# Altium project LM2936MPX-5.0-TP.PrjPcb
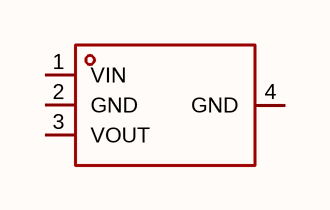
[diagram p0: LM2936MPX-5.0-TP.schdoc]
1 sheet, 1 parts. Net scope: global (net labels, ports and power ports of the same name join across sheets).

## Sheet LM2936MPX-5.0-TP.schdoc
size 127 x 101 mm

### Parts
U?  lm2936mpx-5.0-tp  [SOT-223-4_L6.5-W3.5-P2.30-LS7.0-BR]  (value not drawn)

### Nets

Not connected (* = marked no-connect by the designer): U? 1(VIN) 2(GND) 3(VOUT) 4(GND)

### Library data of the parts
U? = lm2936mpx-5.0-tp: 输出极性:正极;工作电压:36V;输出电压:5V;输出电流:250mA;电源纹波抑制比(PSRR):70dB;输出类型:固定;; Manufacturer: TECH PUBLIC(台舟); AddInBom: yes; ModelId: 925194bf9823436183a3e0b978a8d076; ModelName: SOT-223-4P_L6.5-W3.5-H1.6-LS7.0-P2.30; ModelTransform: 279.89794,255.905,0,180,0,0,-0.0005,-0.0005,0; Output Configuration: 正极; Voltage - Supply: 36V; Output Voltage: 5V; Output Current: 250mA; Power Supply Rejection Ratio (PSRR): 70dB; standby current: 1.5uA; Output Type: 固定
